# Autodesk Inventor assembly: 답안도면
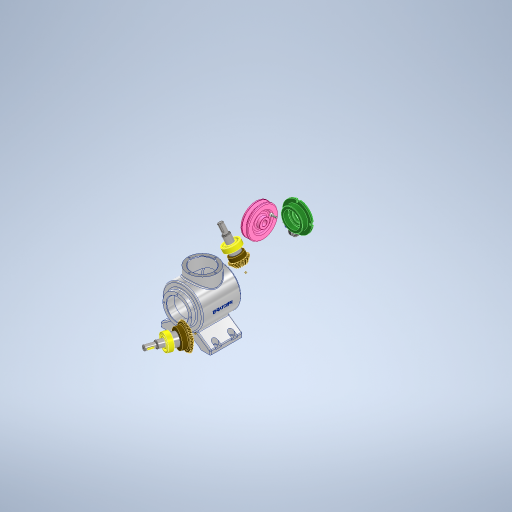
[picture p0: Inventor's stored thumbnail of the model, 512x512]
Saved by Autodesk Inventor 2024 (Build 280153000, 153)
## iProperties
Created: 2023-08
Part Number: 답안도면
Document SubType Name: Assembly
Designer: Owner
Author: Owner
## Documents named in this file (17)
- C:\Users\Owner\Desktop\730813V1006\답안도면.iam
- C:\Users\Owner\Desktop\730813V1006\본체.ipt
- C:\Users\Owner\Desktop\730813V1006\V-벨트풀리.ipt
- C:\Users\Owner\Desktop\730813V1006\메인 베벨기어.ipt
- C:\Users\Owner\Desktop\730813V1006\메인 축.ipt
- 메인 축.ipt
- C:\Users\Owner\Desktop\730813V1006\베어링 6203.ipt
- C:\Users\Owner\Desktop\730813V1006\볼트 M4 x 10.ipt
- C:\Users\Owner\Desktop\730813V1006\서브 베벨기어.ipt
- C:\Users\Owner\Desktop\730813V1006\서브 축.ipt
- 서브 축.ipt
- C:\Users\Owner\Desktop\730813V1006\오일실 17 x 32 x 8.ipt
- C:\Users\Owner\Desktop\730813V1006\와셔 4 x 16.ipt
- C:\Users\Owner\Desktop\730813V1006\육각볼트 M4 x 8.ipt
- C:\Users\Owner\Desktop\730813V1006\커버.ipt
- C:\Users\Owner\Desktop\730813V1006\키 4 x 4 x 14.ipt
- C:\Users\Owner\Desktop\730813V1006\키 5 x 5 x 14.ipt
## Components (1 placed, 1 different names)
1. V-벨트풀리:1
